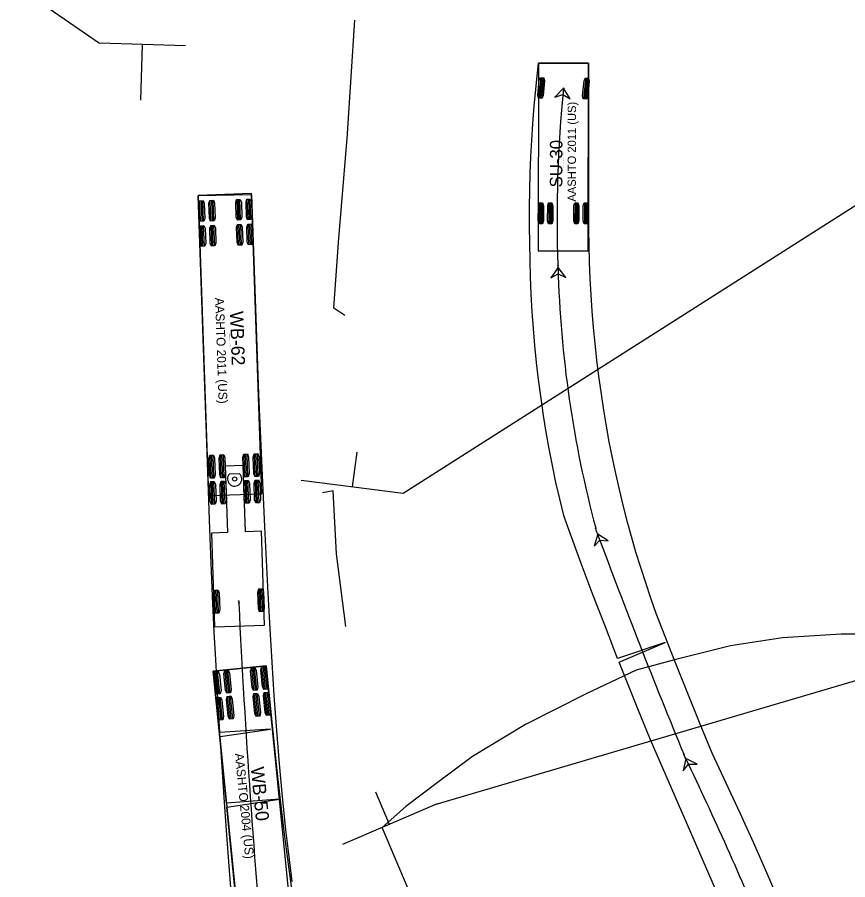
# Model space of a CAD drawing. Extents: x 2096670 to 2098561, y 684033 to 689893.
# Drawn here: x 2097640.1 to 2097772.9, y 686007 to 686144.8 of the extents above; entities that cross this region are included whole.
import ezdxf

# ---------------------------------------------------------------- set-up
doc = ezdxf.new("R2010")
doc.units = 0
for name, color, linetype in [('Default', 7, 'Continuous'), ('Exist Sign E Chevron Left', 7, 'Continuous'), ('Exist Sign E Stop CELL', 7, 'Continuous'), ('Exist Support 1', 7, 'Continuous'), ('Old_Level_63', 7, 'Continuous'), ('Prop DSN Text', 7, 'Continuous'), ('Scratch_Level_4', 7, 'Continuous')]:
    doc.layers.add(name, color=color, linetype=linetype)

msp = doc.modelspace()

# ---------------------------------------------------------------- linework, layer by layer
at = {"layer": 'Default'}
msp.add_line((2097519.27, 686233.6), (2097653.25, 686140.68), dxfattribs=at)
at = {"layer": 'Exist Sign E Chevron Left'}
msp.add_line((2097701.82, 686068.74), (2097875.79, 686179.46), dxfattribs=at)
at = {"layer": 'Exist Sign E Stop CELL'}
msp.add_line((2097841.31, 686058.62), (2097706.88, 686018.92), dxfattribs=at)
at = {"layer": 'Exist Support 1'}
for p, q in [((2097693.73, 686069.79), (2097694.45, 686075.34)), ((2097685.51, 686070.86), (2097701.82, 686068.74)), ((2097699.63, 686015.82), (2097697.42, 686020.97)), ((2097707.25, 686019.09), (2097692.13, 686012.61))]:
    msp.add_line(p, q, dxfattribs=at)
at = {"layer": 'Old_Level_63'}
for p, q in [((2097723.47, 686137.5), (2097723.41, 686107.5)), ((2097731.47, 686137.49), (2097723.47, 686137.5)), ((2097723.47, 686137.5), (2097723.47, 686137.5)), ((2097731.41, 686107.49), (2097731.47, 686137.49)), ((2097723.84, 686135.22), (2097723.51, 686131.91)), ((2097724.05, 686135.2), (2097723.72, 686131.89)), ((2097724.25, 686135.18), (2097723.92, 686131.87)), ((2097731.01, 686135.13), (2097730.67, 686131.81)), ((2097731.21, 686135.11), (2097730.87, 686131.79)), ((2097731.42, 686135.08), (2097731.08, 686131.77)), ((2097677.56, 686116.64), (2097669.06, 686116.35)), ((2097669.06, 686116.35), (2097670.7, 686068.38)), ((2097679.2, 686068.67), (2097677.56, 686116.64)), ((2097669.43, 686112.21), (2097669.32, 686115.51)), ((2097669.66, 686112.22), (2097669.55, 686115.51)), ((2097669.89, 686112.22), (2097669.78, 686115.52)), ((2097671.08, 686112.26), (2097670.97, 686115.56)), ((2097671.31, 686112.27), (2097671.2, 686115.57)), ((2097671.54, 686112.28), (2097671.43, 686115.58)), ((2097675.36, 686112.41), (2097675.25, 686115.71)), ((2097675.59, 686112.42), (2097675.48, 686115.72)), ((2097675.82, 686112.43), (2097675.71, 686115.73)), ((2097677.01, 686112.47), (2097676.9, 686115.77)), ((2097677.24, 686112.48), (2097677.13, 686115.77)), ((2097677.47, 686112.48), (2097677.36, 686115.78)), ((2097723.63, 686115.17), (2097723.63, 686111.84)), ((2097723.84, 686115.17), (2097723.84, 686111.84)), ((2097724.05, 686115.17), (2097724.04, 686111.84)), ((2097725.13, 686115.17), (2097725.13, 686111.83)), ((2097725.34, 686115.17), (2097725.34, 686111.83)), ((2097725.55, 686115.17), (2097725.54, 686111.83)), ((2097729.3, 686115.16), (2097729.29, 686111.83)), ((2097729.51, 686115.16), (2097729.5, 686111.83)), ((2097729.72, 686115.16), (2097729.71, 686111.83)), ((2097730.8, 686115.16), (2097730.79, 686111.82)), ((2097731.01, 686115.16), (2097731, 686111.82)), ((2097731.22, 686115.16), (2097731.21, 686111.82)), ((2097677.15, 686108.47), (2097677.04, 686111.77)), ((2097677.38, 686108.48), (2097677.26, 686111.78)), ((2097677.61, 686108.49), (2097677.49, 686111.78)), ((2097669.57, 686108.21), (2097669.46, 686111.51)), ((2097669.8, 686108.22), (2097669.69, 686111.52)), ((2097670.03, 686108.23), (2097669.91, 686111.52)), ((2097671.22, 686108.27), (2097671.11, 686111.57)), ((2097671.45, 686108.27), (2097671.33, 686111.57)), ((2097671.68, 686108.28), (2097671.56, 686111.58)), ((2097675.5, 686108.41), (2097675.39, 686111.71)), ((2097675.73, 686108.42), (2097675.62, 686111.72)), ((2097675.96, 686108.43), (2097675.84, 686111.73)), ((2097723.41, 686107.5), (2097731.41, 686107.49)), ((2097671.09, 686071.16), (2097670.96, 686074.82)), ((2097671.32, 686071.17), (2097671.19, 686074.83)), ((2097671.55, 686071.17), (2097671.42, 686074.84)), ((2097672.74, 686071.21), (2097672.61, 686074.88)), ((2097672.97, 686071.22), (2097672.84, 686074.89)), ((2097673.19, 686071.23), (2097673.07, 686074.89)), ((2097676.52, 686071.34), (2097676.39, 686075.01)), ((2097676.75, 686071.35), (2097676.62, 686075.02)), ((2097676.98, 686071.36), (2097676.85, 686075.02)), ((2097678.17, 686071.4), (2097678.04, 686075.06)), ((2097678.4, 686071.41), (2097678.27, 686075.07)), ((2097678.62, 686071.42), (2097678.5, 686075.08)), ((2097676.23, 686073.17), (2097673.36, 686073.07)), ((2097676.59, 686062.57), (2097676.23, 686073.17)), ((2097673.36, 686073.07), (2097673.72, 686062.48)), ((2097675.65, 686071.86), (2097674.03, 686071.8)), ((2097671.23, 686066.96), (2097671.11, 686070.62)), ((2097671.46, 686066.97), (2097671.33, 686070.63)), ((2097671.69, 686066.98), (2097671.56, 686070.64)), ((2097672.88, 686067.02), (2097672.75, 686070.68)), ((2097673.11, 686067.02), (2097672.98, 686070.69)), ((2097673.34, 686067.03), (2097673.21, 686070.7)), ((2097676.66, 686067.15), (2097676.54, 686070.81)), ((2097676.89, 686067.15), (2097676.76, 686070.82)), ((2097677.12, 686067.16), (2097676.99, 686070.83)), ((2097678.31, 686067.2), (2097678.18, 686070.87)), ((2097678.54, 686067.21), (2097678.41, 686070.87)), ((2097678.77, 686067.22), (2097678.64, 686070.88)), ((2097670.7, 686068.38), (2097679.2, 686068.67)), ((2097679.2, 686068.67), (2097679.2, 686068.67)), ((2097673.72, 686062.48), (2097671.16, 686062.39)), ((2097671.16, 686062.39), (2097671.67, 686047.4)), ((2097679.15, 686062.66), (2097676.59, 686062.57)), ((2097679.67, 686047.67), (2097679.15, 686062.66)), ((2097671.83, 686049.57), (2097671.7, 686053.23)), ((2097672.06, 686049.58), (2097671.93, 686053.24)), ((2097672.28, 686049.59), (2097672.16, 686053.25)), ((2097678.91, 686049.81), (2097678.78, 686053.48)), ((2097679.13, 686049.82), (2097679.01, 686053.48)), ((2097679.36, 686049.83), (2097679.24, 686053.49)), ((2097671.67, 686047.4), (2097679.67, 686047.67)), ((2097679.67, 686047.67), (2097679.67, 686047.67)), ((2097679.92, 686041.17), (2097671.46, 686040.33)), ((2097671.46, 686040.33), (2097675.67, 685998.04)), ((2097672.06, 686036.62), (2097671.69, 686040.27)), ((2097672.28, 686036.64), (2097671.92, 686040.29)), ((2097672.51, 686036.67), (2097672.15, 686040.32)), ((2097673.7, 686036.79), (2097673.34, 686040.43)), ((2097673.93, 686036.81), (2097673.56, 686040.46)), ((2097674.15, 686036.83), (2097673.79, 686040.48)), ((2097677.96, 686037.21), (2097677.6, 686040.86)), ((2097678.19, 686037.23), (2097677.83, 686040.88)), ((2097678.42, 686037.26), (2097678.05, 686040.9)), ((2097679.6, 686037.37), (2097679.24, 686041.02)), ((2097679.83, 686037.4), (2097679.47, 686041.04)), ((2097680.06, 686037.42), (2097679.7, 686041.07)), ((2097684.13, 685998.88), (2097679.92, 686041.17)), ((2097672.47, 686032.48), (2097672.11, 686036.12)), ((2097672.7, 686032.5), (2097672.33, 686036.15)), ((2097672.93, 686032.52), (2097672.56, 686036.17)), ((2097674.11, 686032.64), (2097673.75, 686036.29)), ((2097674.34, 686032.66), (2097673.98, 686036.31)), ((2097674.57, 686032.68), (2097674.2, 686036.33)), ((2097678.37, 686033.06), (2097678.01, 686036.71)), ((2097678.6, 686033.09), (2097678.24, 686036.73)), ((2097678.83, 686033.11), (2097678.47, 686036.76)), ((2097680.02, 686033.23), (2097679.65, 686036.88)), ((2097680.24, 686033.25), (2097679.88, 686036.9)), ((2097680.47, 686033.27), (2097680.11, 686036.92))]:
    msp.add_line(p, q, dxfattribs=at)
for points in [[(2097753.22, 686002.14), (2097741.34, 686029.32), (2097739.33, 686034.26), (2097736.36, 686041.72), (2097743.7, 686044.91), (2097736.11, 686042.35), (2097734.16, 686047.37), (2097732.22, 686052.42), (2097730.3, 686057.5), (2097727.7, 686064.54), (2097727.49, 686065.19), (2097726.85, 686067.83), (2097726.25, 686070.49), (2097725.7, 686073.16), (2097725.18, 686075.83), (2097724.7, 686078.51), (2097724.26, 686081.2), (2097723.86, 686083.89), (2097723.46, 686086.94), (2097723.15, 686089.66), (2097722.87, 686092.37), (2097722.64, 686095.09), (2097722.44, 686097.82), (2097722.29, 686100.55), (2097722.17, 686103.27), (2097722.1, 686106), (2097722.03, 686111.44), (2097722.03, 686114.48), (2097722.06, 686117.17), (2097722.13, 686119.84), (2097722.24, 686122.51), (2097722.38, 686125.17), (2097722.55, 686127.87), (2097722.77, 686130.61), (2097723.02, 686133.35), (2097723.47, 686137.5), (2097731.47, 686137.49), (2097731.43, 686116.5), (2097731.43, 686110.89), (2097731.48, 686108.28), (2097731.55, 686105.67), (2097731.67, 686103.06), (2097731.81, 686100.46), (2097731.99, 686097.86), (2097732.21, 686095.26), (2097732.45, 686092.66), (2097732.74, 686090.07), (2097733.05, 686087.48), (2097733.45, 686084.59), (2097733.83, 686082.04), (2097734.26, 686079.49), (2097734.72, 686076.95), (2097735.22, 686074.41), (2097735.76, 686071.89), (2097736.33, 686069.37), (2097736.94, 686066.86), (2097737.59, 686064.36), (2097738.27, 686061.87), (2097738.99, 686059.39), (2097739.75, 686056.92), (2097740.55, 686054.46), (2097741.38, 686052.02), (2097742.24, 686049.58), (2097743.15, 686047.15), (2097745.18, 686041.96), (2097747.15, 686037.05), (2097749.14, 686032.15), (2097751.17, 686027.26), (2097753.43, 686022.47), (2097755.65, 686017.67), (2097757.83, 686012.84), (2097760.11, 686007.64), (2097764.34, 685997.73)], [(2097727.46, 686133.5), (2097726.09, 686132.04), (2097727.36, 686132.5), (2097728.51, 686131.8), (2097727.46, 686133.5)], [(2097674.43, 686003.72), (2097674, 686009.13), (2097673.57, 686014.81), (2097673.19, 686020.14), (2097672.56, 686029.84), (2097680.6, 686031.03), (2097672.52, 686030.5), (2097672.2, 686035.87), (2097671.9, 686041.23), (2097671.62, 686046.6), (2097671.35, 686052.29), (2097671.11, 686057.64), (2097670.9, 686062.99), (2097669.06, 686116.35), (2097677.56, 686116.5), (2097677.56, 686116.5)], [(2097677.56, 686116.5), (2097678.3, 686095.23), (2097678.7, 686084.61), (2097679.14, 686073.98), (2097679.63, 686063.36), (2097680.17, 686052.74), (2097680.49, 686047.09), (2097680.8, 686041.77), (2097681.15, 686036.44), (2097681.55, 686030.8), (2097681.98, 686025.5), (2097682.46, 686020.21), (2097683, 686014.93), (2097683.35, 686011.97), (2097684.01, 686006.7)], [(2097726.59, 686104.81), (2097726.58, 686105.14)], [(2097726.59, 686104.81), (2097725.41, 686103.19), (2097726.61, 686103.81), (2097727.85, 686103.25), (2097726.59, 686104.81)], [(2097732.92, 686062.19), (2097732.33, 686060.28), (2097733.26, 686061.25), (2097734.61, 686061.13), (2097732.92, 686062.19)], [(2097732.92, 686062.19), (2097732.8, 686062.5), (2097732.7, 686062.82), (2097732.61, 686063.14)], [(2097675.53, 686051.53), (2097675.54, 686051.2)], [(2097675.08, 686003.98), (2097673.63, 686018.54), (2097682.04, 686019.85), (2097673.56, 686019.2), (2097671.46, 686040.33), (2097679.92, 686041.17), (2097679.92, 686041.13), (2097679.92, 686041.13)], [(2097679.92, 686041.13), (2097680.97, 686030.63), (2097681.52, 686025.4), (2097682.1, 686020.19), (2097682.76, 686014.65), (2097683.43, 686009.45), (2097684.19, 686003.93)], [(2097747.01, 686026.33), (2097746.6, 686024.37), (2097747.45, 686025.42), (2097748.8, 686025.42), (2097747.01, 686026.33)], [(2097747.01, 686026.33), (2097746.87, 686026.63), (2097746.74, 686026.93)]]:
    msp.add_lwpolyline(points, dxfattribs=at)
for points in [[(2097723.79, 686135.23), (2097724.3, 686135.18), (2097724.41, 686134.7), (2097724.18, 686132.31), (2097723.97, 686131.86), (2097723.46, 686131.91), (2097723.35, 686132.39), (2097723.58, 686134.78)], [(2097730.95, 686135.13), (2097731.47, 686135.08), (2097731.58, 686134.6), (2097731.33, 686132.21), (2097731.13, 686131.76), (2097730.61, 686131.82), (2097730.51, 686132.3), (2097730.75, 686134.68)], [(2097727.46, 686133.5), (2097726.09, 686132.04), (2097727.36, 686132.5), (2097728.51, 686131.8)], [(2097669.95, 686112.23), (2097669.38, 686112.21), (2097669.19, 686112.66), (2097669.11, 686115.04), (2097669.26, 686115.5), (2097669.83, 686115.52), (2097670.02, 686115.07), (2097670.1, 686112.69)], [(2097671.6, 686112.28), (2097671.02, 686112.26), (2097670.84, 686112.72), (2097670.76, 686115.09), (2097670.91, 686115.56), (2097671.48, 686115.58), (2097671.67, 686115.12), (2097671.75, 686112.75)], [(2097675.88, 686112.43), (2097675.31, 686112.41), (2097675.12, 686112.87), (2097675.04, 686115.24), (2097675.19, 686115.71), (2097675.76, 686115.73), (2097675.95, 686115.27), (2097676.03, 686112.9)], [(2097677.53, 686112.49), (2097676.95, 686112.47), (2097676.77, 686112.92), (2097676.69, 686115.3), (2097676.84, 686115.76), (2097677.41, 686115.78), (2097677.6, 686115.33), (2097677.68, 686112.95)], [(2097723.58, 686115.17), (2097724.1, 686115.17), (2097724.26, 686114.7), (2097724.25, 686112.3), (2097724.1, 686111.84), (2097723.58, 686111.84), (2097723.42, 686112.3), (2097723.43, 686114.7)], [(2097725.08, 686115.17), (2097725.6, 686115.17), (2097725.76, 686114.7), (2097725.75, 686112.3), (2097725.6, 686111.83), (2097725.08, 686111.83), (2097724.92, 686112.3), (2097724.93, 686114.7)], [(2097729.25, 686115.16), (2097729.77, 686115.16), (2097729.93, 686114.69), (2097729.92, 686112.29), (2097729.76, 686111.83), (2097729.24, 686111.83), (2097729.09, 686112.29), (2097729.09, 686114.69)], [(2097730.75, 686115.16), (2097731.27, 686115.16), (2097731.43, 686114.69), (2097731.42, 686112.29), (2097731.26, 686111.82), (2097730.74, 686111.82), (2097730.59, 686112.29), (2097730.59, 686114.69)], [(2097677.66, 686108.49), (2097677.09, 686108.47), (2097676.9, 686108.92), (2097676.82, 686111.3), (2097676.98, 686111.77), (2097677.55, 686111.79), (2097677.74, 686111.33), (2097677.82, 686108.96)], [(2097670.08, 686108.23), (2097669.51, 686108.21), (2097669.32, 686108.66), (2097669.24, 686111.04), (2097669.4, 686111.51), (2097669.97, 686111.53), (2097670.16, 686111.07), (2097670.24, 686108.7)], [(2097671.73, 686108.28), (2097671.16, 686108.27), (2097670.97, 686108.72), (2097670.89, 686111.1), (2097671.05, 686111.56), (2097671.62, 686111.58), (2097671.81, 686111.13), (2097671.89, 686108.75)], [(2097676.01, 686108.43), (2097675.44, 686108.41), (2097675.25, 686108.87), (2097675.17, 686111.24), (2097675.33, 686111.71), (2097675.9, 686111.73), (2097676.09, 686111.27), (2097676.17, 686108.9)], [(2097726.59, 686104.81), (2097725.41, 686103.19), (2097726.61, 686103.81), (2097727.85, 686103.25)], [(2097671.6, 686071.18), (2097671.03, 686071.16), (2097670.84, 686071.66), (2097670.75, 686074.3), (2097670.91, 686074.82), (2097671.48, 686074.84), (2097671.67, 686074.33), (2097671.76, 686071.69)], [(2097673.25, 686071.23), (2097672.68, 686071.21), (2097672.49, 686071.72), (2097672.4, 686074.36), (2097672.55, 686074.88), (2097673.13, 686074.9), (2097673.32, 686074.39), (2097673.41, 686071.75)], [(2097677.03, 686071.36), (2097676.46, 686071.34), (2097676.27, 686071.85), (2097676.18, 686074.49), (2097676.34, 686075.01), (2097676.91, 686075.03), (2097677.1, 686074.52), (2097677.19, 686071.88)], [(2097678.68, 686071.42), (2097678.11, 686071.4), (2097677.92, 686071.91), (2097677.83, 686074.54), (2097677.98, 686075.06), (2097678.56, 686075.08), (2097678.75, 686074.57), (2097678.84, 686071.94)], [(2097671.75, 686066.98), (2097671.17, 686066.96), (2097670.98, 686067.47), (2097670.89, 686070.1), (2097671.05, 686070.62), (2097671.62, 686070.64), (2097671.81, 686070.14), (2097671.9, 686067.5)], [(2097673.4, 686067.03), (2097672.82, 686067.01), (2097672.63, 686067.52), (2097672.54, 686070.16), (2097672.7, 686070.68), (2097673.27, 686070.7), (2097673.46, 686070.19), (2097673.55, 686067.55)], [(2097677.18, 686067.16), (2097676.6, 686067.14), (2097676.41, 686067.65), (2097676.32, 686070.29), (2097676.48, 686070.81), (2097677.05, 686070.83), (2097677.24, 686070.32), (2097677.33, 686067.68)], [(2097678.83, 686067.22), (2097678.25, 686067.2), (2097678.06, 686067.71), (2097677.97, 686070.35), (2097678.13, 686070.86), (2097678.7, 686070.88), (2097678.89, 686070.38), (2097678.98, 686067.74)], [(2097732.92, 686062.19), (2097732.33, 686060.28), (2097733.26, 686061.25), (2097734.61, 686061.13)], [(2097672.34, 686049.59), (2097671.77, 686049.57), (2097671.58, 686050.08), (2097671.49, 686052.71), (2097671.64, 686053.23), (2097672.22, 686053.25), (2097672.41, 686052.75), (2097672.5, 686050.11)], [(2097679.42, 686049.83), (2097678.85, 686049.81), (2097678.66, 686050.32), (2097678.57, 686052.96), (2097678.72, 686053.48), (2097679.29, 686053.49), (2097679.48, 686052.99), (2097679.58, 686050.35)], [(2097672.57, 686036.67), (2097672, 686036.62), (2097671.78, 686037.11), (2097671.52, 686039.74), (2097671.64, 686040.26), (2097672.21, 686040.32), (2097672.43, 686039.83), (2097672.69, 686037.2)], [(2097674.21, 686036.84), (2097673.64, 686036.78), (2097673.42, 686037.27), (2097673.16, 686039.9), (2097673.28, 686040.43), (2097673.85, 686040.48), (2097674.07, 686039.99), (2097674.33, 686037.36)], [(2097678.47, 686037.26), (2097677.9, 686037.2), (2097677.68, 686037.7), (2097677.42, 686040.32), (2097677.54, 686040.85), (2097678.11, 686040.91), (2097678.33, 686040.42), (2097678.59, 686037.79)], [(2097680.12, 686037.42), (2097679.55, 686037.37), (2097679.32, 686037.86), (2097679.06, 686040.49), (2097679.18, 686041.02), (2097679.75, 686041.07), (2097679.97, 686040.58), (2097680.24, 686037.95)], [(2097672.98, 686032.53), (2097672.41, 686032.47), (2097672.19, 686032.96), (2097671.93, 686035.59), (2097672.05, 686036.12), (2097672.62, 686036.17), (2097672.84, 686035.68), (2097673.1, 686033.05)], [(2097674.62, 686032.69), (2097674.06, 686032.63), (2097673.83, 686033.13), (2097673.57, 686035.75), (2097673.69, 686036.28), (2097674.26, 686036.34), (2097674.48, 686035.84), (2097674.75, 686033.22)], [(2097678.89, 686033.11), (2097678.32, 686033.06), (2097678.1, 686033.55), (2097677.83, 686036.18), (2097677.95, 686036.71), (2097678.52, 686036.76), (2097678.75, 686036.27), (2097679.01, 686033.64)], [(2097680.53, 686033.28), (2097679.96, 686033.22), (2097679.74, 686033.72), (2097679.48, 686036.34), (2097679.6, 686036.87), (2097680.17, 686036.93), (2097680.39, 686036.43), (2097680.65, 686033.81)], [(2097747.01, 686026.33), (2097746.6, 686024.37), (2097747.45, 686025.42), (2097748.8, 686025.42)]]:
    msp.add_lwpolyline(points, close=True, dxfattribs=at)
for centre, radius in [((2097727.46, 686133.5), 0.0417), ((2097726.58, 686105.14), 0.0417), ((2097726.58, 686105.14), 0.0417), ((2097726.59, 686104.81), 0.0417), ((2097726.59, 686104.81), 0.0417), ((2097674.87, 686071.02), 0.34), ((2097732.61, 686063.14), 0.0417), ((2097732.61, 686063.14), 0.0417), ((2097732.92, 686062.19), 0.0417), ((2097732.92, 686062.19), 0.0417), ((2097675.53, 686051.53), 0.0417), ((2097675.54, 686051.2), 0.0417), ((2097675.54, 686051.2), 0.0417), ((2097746.74, 686026.93), 0.0417), ((2097746.74, 686026.93), 0.0417), ((2097747.01, 686026.33), 0.0417), ((2097747.01, 686026.33), 0.0417)]:
    msp.add_circle(centre, radius, dxfattribs=at)
for centre, radius, start, end in [((2097930.32, 686112.98), 203.9, 174.2241, 182.2032), ((2097906.73, 686109.59), 180.21, 181.5199, 194.9343), ((2097674.87, 686071.02), 1.14, 136.9601, 46.9601), ((2098685.08, 686415.09), 1015.46, 200.3363, 202.47327), ((2099104.41, 686119.61), 1430.51, 182.74116, 185.22576), ((2097233.71, 685779.65), 569.5, 22.5044, 25.6678)]:
    msp.add_arc(centre, radius, start, end, dxfattribs=at)
at = {"layer": 'Prop DSN Text'}
for p, q in [((2097667.01, 686140.28), (2097653.25, 686140.68)), ((2097660.07, 686140.48), (2097659.82, 686131.56))]:
    msp.add_line(p, q, dxfattribs=at)
at = {"layer": 'Scratch_Level_4'}
msp.add_line((2097692.91, 686126.24), (2097694.11, 686144.37), dxfattribs=at)
for points in [[(2097692.51, 686097.14), (2097690.72, 686098.35), (2097691.47, 686108.82), (2097692.9, 686126.14)], [(2097692.64, 686047.47), (2097691.15, 686059.05), (2097690.62, 686069.11), (2097688.91, 686068.82)], [(2097784.02, 686046.24), (2097771.84, 686046.24), (2097762.46, 686045.62), (2097754.16, 686044.36), (2097745.41, 686042.15), (2097739.08, 686040.48), (2097731.07, 686036.67), (2097721.38, 686031.8), (2097712.91, 686026.66), (2097707.25, 686022.44), (2097702.25, 686018.67), (2097698.44, 686015.3)], [(2097735.51, 685929.5), (2097715.39, 685975.37), (2097698.44, 686015.3)]]:
    msp.add_lwpolyline(points, dxfattribs=at)
msp.add_arc((2097686.92, 686126.64), 6, 355.2604, 356.2157, dxfattribs=at)

# ---------------------------------------------------------------- texts
at = {"layer": 'Old_Level_63'}
for s, height, rotation, p in [('AASHTO 2011 (US)', 1.3333, 89.8888, (2097729.43, 686115.37)), ('SU-30', 2, 89.8888, (2097727.27, 686117.64)), ('(c) 2022 Transoft Solutions, Inc. All rights reserved.', 0.08, 89.8888, (2097727.48, 686120.86)), ('AASHTO 2011 (US)', 1.4167, 271.9601, (2097671.74, 686099.99)), ('WB-62', 2.125, 271.9601, (2097674.12, 686097.82)), ('(c) 2023 Transoft Solutions, Inc. All rights reserved.', 0.085, 271.9601, (2097674.03, 686094.25)), ('AASHTO 2004 (US)', 1.4167, 275.6909, (2097674.9, 686027.12)), ('WB-50', 2.125, 275.6909, (2097677.44, 686024.91)), ('(c) 2023 Transoft Solutions, Inc. All rights reserved.', 0.085, 275.6909, (2097677.58, 686021.33))]:
    msp.add_text(s, height=height, rotation=rotation, dxfattribs=at).set_placement(p)

doc.saveas('drawing.dxf')
